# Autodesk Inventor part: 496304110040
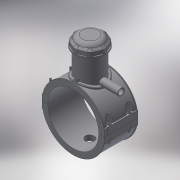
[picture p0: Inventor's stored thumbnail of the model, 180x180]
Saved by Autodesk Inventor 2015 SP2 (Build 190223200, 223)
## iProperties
Created: 2017-07
Part Number: 496304110040
Material: Generic
Description: PLASSON TAPPING SADDLE 110x40
Document SubType Name: Modeling
Designer: KIM
Mass: 725.836 g
Surface Area: 1795.32 cm^2
Volume: 725.836 cm^3
Density: 1 g/cm^3
Appearance: Default
Author: KIM
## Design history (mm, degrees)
derived "496304.ipt"
feature "Solid1::496304.ipt"
feature "Solid2::496304.ipt"
feature "Solid4::496304.ipt"
feature "Solid5::496304.ipt"
tag "TaggingFeature1"
body "Solid1"
body "Solid2"
other parameters: "d2" = 148, "d3" = 27.5, "d4" = 118, "d5" = 0, "d6" = 0.1, "d8" = 0, "d19" = 6, "d20" = 6, "d21" = 70.8, "d23" = 0, "d24" = 35.4, "d26" = 0, "d29" = 3, "d30" = 36.66667, "d31" = 6, "d32" = 0, "d33" = 0, "d34" = 0.6, "d40" = 68.64, "d41" = 66, "d43" = 0, "d45" = 0, "d47" = 136.8, "d70" = 15, "d72" = 0, "d73" = 6, "d75" = 5, "d76" = 0, "d77" = 5.5, "d78" = 85, "d79" = 15, "d80" = 47.2, "d82" = 5 deg, "d84" = 4, "d85" = 14, "d86" = 0, "d87" = 3, "d88" = 0, "d89" = 1, "d90" = 1, "d91" = 94.4, "d92" = 0, "d93" = 0.5, "d94" = 57.89474, "d96" = 134.64, "d97" = 2.36, "d98" = 0, "d102" = 1.1, "d120" = 140 deg, "d121" = 24.228, "d122" = 20 deg, "d123" = 264, "d124" = 79.2, "d126" = 0, "d143" = 113.3, "d145" = 16.92308, "d149" = 1.65, "d150" = 18.61538, "d153" = 118, "d154" = 0, "d156" = 66, "d157" = 160 deg, "d159" = 4.4, "d161" = 1.65, "d162" = 70.8, "d163" = 0, "d164" = 55, "d167" = 11, "d168" = 64.39024, "d170" = 3.375, "d172" = 0, "d173" = 1, "d175" = 55, "d176" = 20 deg, "d177" = 7.7, "d178" = 22, "d180" = 0, "d183" = 8.8, "d184" = 6.16, "d185" = 38.35, "d186" = 38.35, "d187" = 66, "d188" = 6.6, "d189" = 7.7, "d190" = 0, "d191" = 99, "d193" = 6.3, "d194" = 4.13, "d195" = 90 deg, "d197" = 0, "d199" = 0, "d200" = 11, "d202" = 0, "d203" = 114, "d204" = 62.7, "d205" = 46.2, "d206" = 56.1, "d207" = 85.5, "d208" = 88.92, "d209" = 106.02, "d210" = 56.76, "d211" = 66, "d212" = 52.8, "d213" = 0.9, "d216" = 0, "d217" = 11, "d218" = 11, "d219" = 2.2, "d224" = 0, "d230" = 4.4, "d233" = 6, "d236" = 74, "d237" = 35.4, "d238" = 6.02433, "d240" = 35.4, "d241" = 35.4, "d242" = 35.4, "d243" = 6, "d244" = 35.4, "d245" = 35.4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
